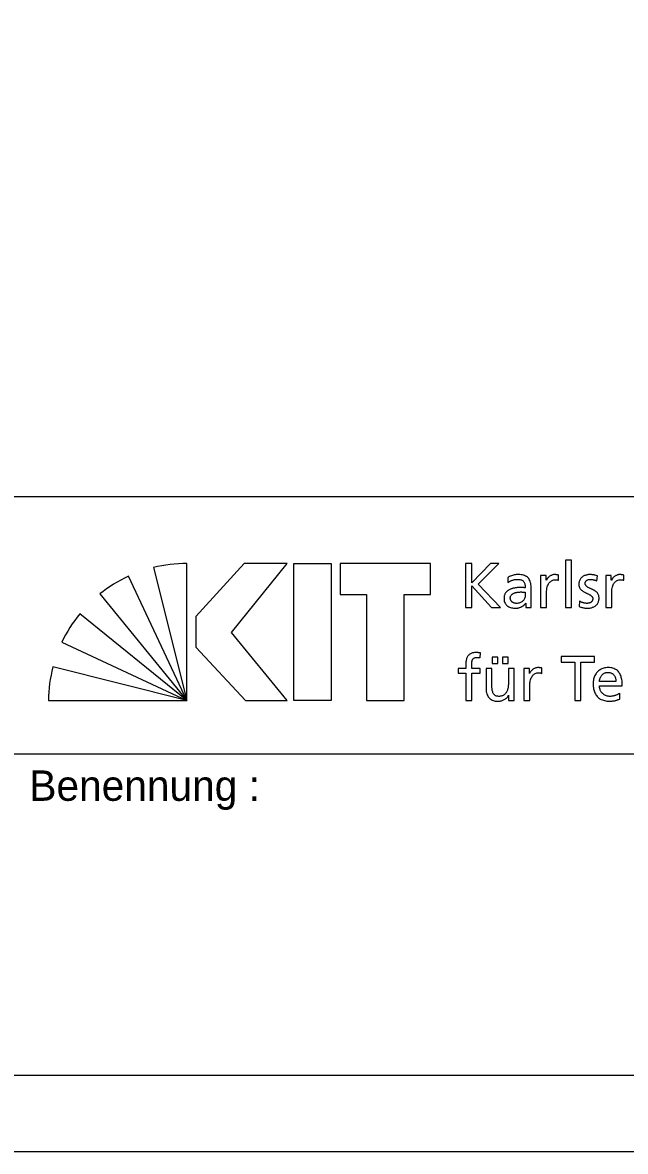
# Model space of a CAD drawing. Extents: x 0 to 105, y 0 to 148.
# Drawn here: x 60.83 to 80.66, y 0 to 37.12 of the extents above; entities that cross this region are included whole.
import ezdxf

# ---------------------------------------------------------------- set-up
doc = ezdxf.new("R2010")
doc.units = 0
doc.layers.add('90_Plankopf', color=7, linetype='Continuous')

msp = doc.modelspace()

# ---------------------------------------------------------------- linework, layer by layer
at = {"layer": '90_Plankopf'}
for p, q in [((12.5, 21.535), (102.5, 21.535)), ((66.24, 14.833), (66.24, 19.332)), ((75.405, 19.333), (75.405, 17.893)), ((65.137, 19.206), (66.24, 14.833)), ((78.463, 18.782), (78.463, 18.956)), ((80.606, 18.782), (80.606, 18.956)), ((66.24, 14.833), (64.317, 18.916)), ((76.79, 18.871), (76.8, 18.706)), ((79.728, 18.76), (79.745, 18.929)), ((63.372, 18.333), (66.24, 14.833)), ((77.365, 18.394), (77.365, 18.301)), ((77.559, 18.099), (77.559, 18.535)), ((75.405, 17.893), (75.611, 17.893)), ((76.253, 17.893), (76.554, 17.893)), ((79.149, 18.099), (79.138, 17.926)), ((66.24, 14.833), (62.717, 17.683)), ((62.12, 16.747), (66.24, 14.833)), ((75.887, 16.236), (75.895, 16.393)), ((66.24, 14.833), (61.829, 15.934)), ((77.913, 15.722), (77.913, 15.896)), ((80.353, 15.46), (79.808, 15.46)), ((79.808, 15.316), (80.559, 15.316)), ((80.479, 14.877), (80.479, 15.07)), ((61.682, 14.833), (66.24, 14.833)), ((54.324, 13.075), (102.5, 13.075))]:
    msp.add_line(p, q, dxfattribs=at)
for points in [[(0, 0), (105, 0), (105, 148.5), (0, 148.5)], [(12.5, 146), (102.5, 146), (102.5, 2.5), (12.5, 2.5)], [(69.533, 19.333), (68.118, 19.333), (66.536, 17.589), (66.536, 16.586), (68.169, 14.833), (69.542, 14.833), (67.711, 17.071)], [(70.985, 19.333), (70.985, 14.833), (69.751, 14.833), (69.751, 19.333)], [(71.281, 19.333), (71.281, 18.32), (72.151, 18.32), (72.151, 14.833), (73.385, 14.833), (73.385, 18.32), (74.255, 18.32), (74.255, 19.333)]]:
    msp.add_lwpolyline(points, close=True, dxfattribs=at)
for points in [[(76.554, 17.893), (75.824, 18.652), (76.5, 19.333), (76.226, 19.333), (75.611, 18.7), (75.611, 19.333), (75.405, 19.333)], [(78.69, 17.893), (78.884, 17.893), (78.884, 19.44), (78.69, 19.44), (78.69, 17.893)], [(78.061, 18.782), (78.057, 18.782), (78.057, 18.945), (77.875, 18.945), (77.875, 17.893), (78.069, 17.893), (78.069, 18.372)], [(80.203, 18.782), (80.199, 18.782), (80.199, 18.945), (80.018, 18.945), (80.018, 17.893), (80.212, 17.893), (80.212, 18.372)], [(75.611, 17.893), (75.611, 18.599), (76.253, 17.893)], [(77.382, 18.029), (77.386, 18.029), (77.386, 17.893), (77.567, 17.893)], [(75.412, 15.983), (75.412, 15.886), (75.165, 15.886), (75.165, 15.729), (75.412, 15.729), (75.412, 14.833), (75.606, 14.833), (75.606, 15.729), (75.885, 15.729), (75.885, 15.886), (75.606, 15.886), (75.606, 15.999)], [(76.277, 16.253), (76.277, 16.046), (76.471, 16.046), (76.471, 16.253), (76.277, 16.253)], [(76.615, 16.253), (76.615, 16.046), (76.809, 16.046), (76.809, 16.253), (76.615, 16.253)], [(78.995, 14.833), (79.201, 14.833), (79.201, 16.092), (79.649, 16.092), (79.649, 16.273), (78.547, 16.273), (78.547, 16.092), (78.995, 16.092), (78.995, 14.833)], [(76.271, 15.341), (76.271, 15.886), (76.077, 15.886), (76.077, 15.26)], [(77.007, 14.833), (77.007, 15.886), (76.813, 15.886), (76.813, 15.399)], [(77.511, 15.722), (77.507, 15.722), (77.507, 15.886), (77.325, 15.886), (77.325, 14.833), (77.519, 14.833), (77.519, 15.312)], [(76.816, 15), (76.82, 15), (76.82, 14.833), (77.007, 14.833)]]:
    msp.add_lwpolyline(points, dxfattribs=at)
for centre, start, end in [((66.224, 14.568), 89.8053, 103.1895), ((66.331, 14.599), 115.0126, 128.3968), ((66.408, 14.671), 140.7898, 154.174), ((66.446, 14.759), 165.7222, 179.1064)]:
    msp.add_arc(centre, 4.764, start, end, dxfattribs=at)
for points in [[(77.559, 18.535), (77.56, 18.63), (77.545, 18.71), (77.517, 18.775), (77.488, 18.84), (77.442, 18.888), (77.38, 18.921), (77.317, 18.953), (77.236, 18.97), (77.136, 18.97), (77.069, 18.97), (77.007, 18.96), (76.949, 18.942), (76.891, 18.924), (76.838, 18.901), (76.79, 18.871)], [(78.463, 18.956), (78.45, 18.958), (78.437, 18.961), (78.425, 18.963), (78.412, 18.965), (78.399, 18.967), (78.385, 18.968), (78.371, 18.969), (78.354, 18.97), (78.335, 18.97), (78.298, 18.97), (78.261, 18.962), (78.226, 18.946), (78.191, 18.93), (78.159, 18.908), (78.13, 18.879), (78.101, 18.851), (78.078, 18.819), (78.061, 18.782)], [(79.745, 18.929), (79.707, 18.94), (79.669, 18.95), (79.63, 18.958), (79.591, 18.966), (79.549, 18.97), (79.504, 18.97), (79.451, 18.97), (79.403, 18.963), (79.358, 18.95), (79.313, 18.937), (79.274, 18.917), (79.24, 18.89), (79.206, 18.863), (79.18, 18.83), (79.161, 18.789), (79.142, 18.748), (79.132, 18.701), (79.132, 18.646), (79.132, 18.604), (79.141, 18.568), (79.158, 18.537), (79.174, 18.506), (79.195, 18.48), (79.223, 18.457), (79.25, 18.435), (79.279, 18.415), (79.312, 18.397), (79.344, 18.38), (79.376, 18.364), (79.409, 18.349), (79.441, 18.333), (79.471, 18.317), (79.498, 18.301), (79.525, 18.285), (79.547, 18.267), (79.563, 18.246), (79.579, 18.226), (79.588, 18.203), (79.588, 18.176), (79.588, 18.147), (79.582, 18.124), (79.57, 18.104), (79.558, 18.085), (79.542, 18.069), (79.522, 18.058), (79.503, 18.046), (79.482, 18.038), (79.459, 18.033), (79.435, 18.027), (79.412, 18.025), (79.39, 18.025), (79.371, 18.025), (79.347, 18.028), (79.32, 18.033), (79.292, 18.039), (79.263, 18.047), (79.233, 18.058), (79.203, 18.069), (79.175, 18.083), (79.149, 18.099)], [(80.606, 18.956), (80.592, 18.958), (80.579, 18.961), (80.567, 18.963), (80.555, 18.965), (80.541, 18.967), (80.527, 18.968), (80.513, 18.969), (80.497, 18.97), (80.478, 18.97), (80.44, 18.97), (80.404, 18.962), (80.368, 18.946), (80.333, 18.93), (80.301, 18.908), (80.273, 18.879), (80.244, 18.851), (80.221, 18.819), (80.203, 18.782)], [(76.8, 18.706), (76.826, 18.728), (76.856, 18.747), (76.89, 18.763), (76.923, 18.779), (76.958, 18.791), (76.995, 18.8), (77.032, 18.809), (77.068, 18.813), (77.105, 18.813), (77.17, 18.813), (77.221, 18.803), (77.259, 18.783), (77.297, 18.762), (77.324, 18.731), (77.341, 18.691), (77.358, 18.65), (77.365, 18.599), (77.365, 18.539)], [(78.069, 18.372), (78.069, 18.46), (78.081, 18.536), (78.105, 18.6), (78.129, 18.664), (78.162, 18.714), (78.205, 18.748), (78.247, 18.783), (78.298, 18.8), (78.356, 18.801), (78.373, 18.801), (78.39, 18.8), (78.409, 18.797), (78.427, 18.794), (78.445, 18.789), (78.463, 18.782)], [(79.138, 17.926), (79.183, 17.903), (79.23, 17.887), (79.279, 17.879), (79.328, 17.871), (79.377, 17.867), (79.427, 17.868), (79.475, 17.868), (79.52, 17.875), (79.564, 17.888), (79.607, 17.901), (79.647, 17.921), (79.681, 17.948), (79.716, 17.975), (79.743, 18.009), (79.764, 18.05), (79.784, 18.091), (79.794, 18.14), (79.795, 18.196), (79.794, 18.244), (79.786, 18.285), (79.769, 18.318), (79.753, 18.351), (79.731, 18.38), (79.704, 18.403), (79.677, 18.426), (79.647, 18.446), (79.615, 18.462), (79.583, 18.479), (79.55, 18.494), (79.518, 18.508), (79.486, 18.523), (79.456, 18.538), (79.429, 18.553), (79.402, 18.569), (79.38, 18.587), (79.364, 18.608), (79.347, 18.629), (79.339, 18.655), (79.338, 18.685), (79.339, 18.714), (79.348, 18.738), (79.365, 18.757), (79.382, 18.776), (79.404, 18.79), (79.432, 18.799), (79.46, 18.809), (79.491, 18.813), (79.524, 18.813), (79.536, 18.813), (79.551, 18.811), (79.569, 18.809), (79.588, 18.806), (79.607, 18.801), (79.627, 18.796), (79.648, 18.791), (79.667, 18.786), (79.685, 18.779), (79.703, 18.773), (79.717, 18.766), (79.728, 18.76)], [(80.212, 18.372), (80.212, 18.46), (80.224, 18.536), (80.247, 18.6), (80.271, 18.664), (80.304, 18.714), (80.347, 18.748), (80.39, 18.783), (80.44, 18.8), (80.498, 18.801), (80.515, 18.801), (80.533, 18.8), (80.551, 18.797), (80.57, 18.794), (80.588, 18.789), (80.606, 18.782)], [(77.365, 18.539), (77.34, 18.54), (77.317, 18.541), (77.295, 18.541), (77.273, 18.542), (77.251, 18.543), (77.229, 18.543), (77.208, 18.543), (77.184, 18.543), (77.159, 18.543), (77.118, 18.543), (77.076, 18.539), (77.031, 18.532), (76.987, 18.525), (76.943, 18.513), (76.9, 18.497), (76.858, 18.481), (76.819, 18.459), (76.784, 18.432), (76.75, 18.406), (76.722, 18.373), (76.701, 18.334), (76.681, 18.295), (76.671, 18.249), (76.67, 18.196), (76.671, 18.12), (76.687, 18.058), (76.719, 18.009), (76.752, 17.961), (76.797, 17.925), (76.855, 17.902), (76.913, 17.879), (76.979, 17.868), (77.056, 17.868), (77.1, 17.868), (77.14, 17.874), (77.175, 17.884), (77.21, 17.895), (77.241, 17.908), (77.268, 17.924), (77.295, 17.941), (77.318, 17.959), (77.337, 17.977), (77.355, 17.995), (77.37, 18.012), (77.382, 18.029)], [(77.365, 18.301), (77.365, 18.249), (77.354, 18.201), (77.332, 18.16), (77.31, 18.118), (77.277, 18.086), (77.233, 18.062), (77.19, 18.038), (77.136, 18.025), (77.072, 18.025), (77.05, 18.025), (77.027, 18.029), (77.004, 18.036), (76.981, 18.043), (76.96, 18.054), (76.941, 18.069), (76.922, 18.083), (76.906, 18.101), (76.894, 18.122), (76.883, 18.144), (76.877, 18.168), (76.876, 18.196), (76.877, 18.233), (76.886, 18.264), (76.904, 18.289), (76.922, 18.313), (76.946, 18.333), (76.975, 18.347), (77.003, 18.362), (77.034, 18.373), (77.067, 18.381), (77.1, 18.388), (77.132, 18.393), (77.163, 18.395), (77.194, 18.398), (77.22, 18.399), (77.241, 18.398), (77.262, 18.398), (77.283, 18.398), (77.303, 18.396), (77.324, 18.395), (77.345, 18.395), (77.365, 18.394)], [(77.567, 17.893), (77.566, 17.903), (77.565, 17.917), (77.563, 17.933), (77.562, 17.951), (77.561, 17.973), (77.561, 18), (77.56, 18.026), (77.559, 18.06), (77.559, 18.099)], [(75.895, 16.393), (75.875, 16.396), (75.855, 16.399), (75.834, 16.402), (75.812, 16.404), (75.79, 16.406), (75.765, 16.406), (75.694, 16.405), (75.635, 16.395), (75.589, 16.376), (75.543, 16.356), (75.507, 16.327), (75.481, 16.29), (75.455, 16.253), (75.437, 16.208), (75.427, 16.156), (75.417, 16.105), (75.412, 16.047), (75.412, 15.983)], [(75.606, 15.999), (75.606, 16.035), (75.608, 16.068), (75.612, 16.098), (75.616, 16.128), (75.625, 16.155), (75.637, 16.177), (75.65, 16.2), (75.669, 16.217), (75.694, 16.23), (75.719, 16.242), (75.752, 16.249), (75.794, 16.249), (75.811, 16.249), (75.828, 16.248), (75.844, 16.246), (75.861, 16.243), (75.875, 16.24), (75.887, 16.236)], [(77.913, 15.896), (77.9, 15.899), (77.887, 15.901), (77.875, 15.903), (77.863, 15.905), (77.849, 15.907), (77.835, 15.908), (77.821, 15.91), (77.804, 15.91), (77.786, 15.91), (77.748, 15.91), (77.712, 15.902), (77.676, 15.886), (77.641, 15.87), (77.609, 15.848), (77.581, 15.82), (77.552, 15.792), (77.529, 15.759), (77.511, 15.722)], [(77.519, 15.312), (77.52, 15.4), (77.532, 15.477), (77.555, 15.541), (77.579, 15.605), (77.612, 15.654), (77.655, 15.688), (77.698, 15.723), (77.748, 15.741), (77.806, 15.741), (77.823, 15.741), (77.841, 15.74), (77.859, 15.737), (77.878, 15.735), (77.896, 15.73), (77.913, 15.722)], [(80.559, 15.316), (80.56, 15.401), (80.552, 15.48), (80.536, 15.552), (80.52, 15.624), (80.495, 15.686), (80.459, 15.74), (80.423, 15.794), (80.375, 15.835), (80.315, 15.865), (80.256, 15.895), (80.182, 15.91), (80.095, 15.91), (80.02, 15.91), (79.953, 15.897), (79.892, 15.871), (79.832, 15.845), (79.78, 15.809), (79.737, 15.761), (79.694, 15.714), (79.66, 15.658), (79.637, 15.592), (79.614, 15.528), (79.602, 15.456), (79.602, 15.378), (79.602, 15.292), (79.613, 15.214), (79.634, 15.144), (79.656, 15.075), (79.69, 15.015), (79.734, 14.965), (79.779, 14.915), (79.835, 14.876), (79.904, 14.849), (79.973, 14.822), (80.053, 14.809), (80.147, 14.808), (80.204, 14.809), (80.253, 14.813), (80.293, 14.82), (80.334, 14.828), (80.369, 14.837), (80.398, 14.847), (80.428, 14.857), (80.454, 14.867), (80.479, 14.877)], [(79.808, 15.46), (79.812, 15.495), (79.82, 15.529), (79.832, 15.564), (79.844, 15.598), (79.861, 15.629), (79.884, 15.658), (79.906, 15.687), (79.934, 15.71), (79.969, 15.727), (80.003, 15.744), (80.043, 15.753), (80.091, 15.753), (80.133, 15.753), (80.17, 15.746), (80.202, 15.73), (80.235, 15.715), (80.262, 15.694), (80.285, 15.667), (80.307, 15.641), (80.324, 15.609), (80.335, 15.574), (80.347, 15.539), (80.353, 15.501), (80.353, 15.46)], [(76.077, 15.26), (76.077, 15.166), (76.091, 15.085), (76.118, 15.018), (76.146, 14.95), (76.19, 14.899), (76.248, 14.863), (76.306, 14.827), (76.38, 14.809), (76.471, 14.808), (76.52, 14.809), (76.568, 14.816), (76.613, 14.831), (76.658, 14.847), (76.698, 14.869), (76.733, 14.897), (76.768, 14.926), (76.796, 14.96), (76.816, 15)], [(76.813, 15.399), (76.813, 15.334), (76.807, 15.276), (76.795, 15.223), (76.782, 15.17), (76.763, 15.124), (76.736, 15.086), (76.71, 15.047), (76.677, 15.018), (76.637, 14.997), (76.596, 14.976), (76.549, 14.966), (76.494, 14.965), (76.438, 14.969), (76.393, 14.984), (76.361, 15.013), (76.328, 15.041), (76.305, 15.082), (76.291, 15.137), (76.277, 15.191), (76.271, 15.259), (76.271, 15.341)], [(80.479, 15.07), (80.467, 15.061), (80.449, 15.05), (80.426, 15.037), (80.403, 15.025), (80.377, 15.014), (80.347, 15.003), (80.317, 14.992), (80.286, 14.983), (80.253, 14.976), (80.22, 14.969), (80.187, 14.966), (80.155, 14.965), (80.108, 14.966), (80.065, 14.974), (80.023, 14.991), (79.982, 15.008), (79.945, 15.032), (79.913, 15.063), (79.88, 15.094), (79.855, 15.13), (79.836, 15.173), (79.818, 15.216), (79.809, 15.264), (79.808, 15.316)]]:
    msp.add_open_spline(points, degree=3, dxfattribs=at)

# ---------------------------------------------------------------- texts
msp.add_text('Benennung :', height=1, dxfattribs=at).set_placement((61.056, 11.53))

doc.saveas('drawing.dxf')
